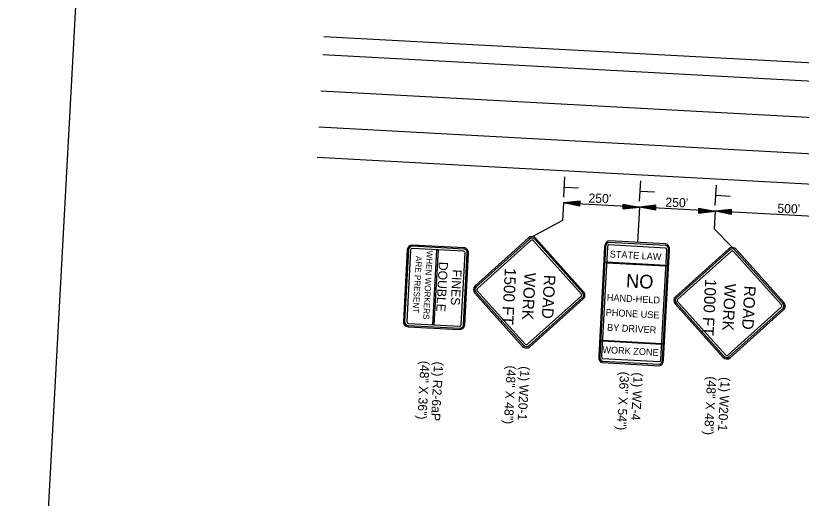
# Model space of a CAD drawing. Extents: x 879461 to 881100, y 1566470 to 1567598.
# Drawn here: x 879461 to 879979, y 1566961 to 1567279 of the extents above; entities that cross this region are included whole.
import ezdxf

# ---------------------------------------------------------------- set-up
doc = ezdxf.new("R2010")
doc.units = 0
for name, color, linetype in [('P_TC_Signs_Permanent', 7, 'Continuous'), ('P_TC_Signs_Temporary', 7, 'Continuous'), ('R_Annotation', 7, 'Continuous'), ('R_Draft', 7, 'Continuous'), ('R_No Plot', 7, 'Continuous')]:
    doc.layers.add(name, color=color, linetype=linetype)

msp = doc.modelspace()

# ---------------------------------------------------------------- linework, layer by layer
at = {"layer": 'P_TC_Signs_Permanent'}
for p, q in [((879889.73, 1567127.9), (879852.27, 1567129.94)), ((879889.79, 1567128.9), (879852.33, 1567130.94)), ((879719.32, 1567125.01), (879716.76, 1567077.83)), ((879720.17, 1567124.96), (879717.6, 1567077.78)), ((879721.57, 1567124.89), (879719, 1567077.71)), ((879756.45, 1567124.12), (879722.75, 1567125.95)), ((879756.53, 1567125.52), (879722.83, 1567127.35)), ((879756.58, 1567126.36), (879722.88, 1567128.19)), ((879849.43, 1567127.07), (879845.51, 1567054.83)), ((879850.1, 1567127.04), (879846.17, 1567054.79)), ((879851.22, 1567126.97), (879847.29, 1567054.73)), ((879889.64, 1567126.23), (879852.18, 1567128.26)), ((879886.53, 1567052.6), (879890.46, 1567124.84)), ((879887.65, 1567052.54), (879891.58, 1567124.78)), ((879888.32, 1567052.5), (879892.25, 1567124.74)), ((879754.95, 1567075.75), (879757.52, 1567122.93)), ((879756.35, 1567075.67), (879758.92, 1567122.85)), ((879757.2, 1567075.63), (879759.76, 1567122.81)), ((879719.94, 1567074.27), (879753.64, 1567072.44)), ((879719.99, 1567075.12), (879753.69, 1567073.28)), ((879720.07, 1567076.52), (879753.77, 1567074.69)), ((879848.02, 1567051.67), (879885.48, 1567049.64)), ((879848.11, 1567053.34), (879885.57, 1567051.31)), ((879847.96, 1567050.67), (879885.42, 1567048.63))]:
    msp.add_line(p, q, dxfattribs=at)
for centre, radius, start, end in [((879722.69, 1567124.82), 3.37, 86.8871, 176.8871), ((879722.69, 1567124.82), 2.53, 86.8871, 176.8871), ((879722.69, 1567124.82), 1.12, 86.8871, 176.8871), ((879756.39, 1567122.99), 1.12, 356.8871, 86.8871), ((879756.39, 1567122.99), 2.53, 356.8871, 86.8871), ((879756.39, 1567122.99), 3.37, 356.8871, 86.8871), ((879720.13, 1567077.64), 3.37, 176.8871, 266.8871), ((879720.13, 1567077.64), 2.53, 176.8871, 266.8871), ((879720.13, 1567077.64), 1.12, 176.8871, 266.8871), ((879753.83, 1567075.81), 3.37, 266.8871, 356.8871), ((879753.83, 1567075.81), 2.53, 266.8871, 356.8871), ((879753.83, 1567075.81), 1.13, 266.8871, 356.8871)]:
    msp.add_arc(centre, radius, start, end, dxfattribs=at)
for centre, major_axis, start_param, end_param in [((879852.11, 1567126.93), (0.22, 4.01), 0, 1.570796), ((879852.11, 1567126.93), (0.16, 3.01), 0, 1.570796), ((879852.11, 1567126.93), (0.07, 1.34), 0, 1.570796), ((879889.57, 1567124.89), (0.07, 1.34), 4.712389, 6.283185), ((879889.57, 1567124.89), (0.16, 3.01), 4.712389, 6.283185), ((879889.57, 1567124.89), (0.22, 4.01), 4.712389, 6.283185), ((879848.18, 1567054.68), (-0.22, -4.01), 4.712389, 6.283185), ((879848.18, 1567054.68), (-0.16, -3.01), 4.712389, 6.283185), ((879848.18, 1567054.68), (-0.07, -1.34), 4.712389, 6.283185), ((879885.64, 1567052.65), (-0.22, -4.01), 0, 1.570796), ((879885.64, 1567052.65), (-0.16, -3.01), 0, 1.570796), ((879885.64, 1567052.65), (-0.07, -1.34), 0, 1.570796)]:
    msp.add_ellipse(centre, major_axis=major_axis, ratio=0.666667, start_param=start_param, end_param=end_param, dxfattribs=at)
at = {"layer": 'P_TC_Signs_Temporary'}
for p, q in [((879764.09, 1567101.3), (879799.27, 1567132.85)), ((879764.72, 1567100.61), (879799.89, 1567132.15)), ((879765.59, 1567099.63), (879800.77, 1567131.18)), ((879802.36, 1567131.09), (879833.9, 1567095.91)), ((879803.33, 1567131.97), (879834.88, 1567096.79)), ((879804.03, 1567132.59), (879835.58, 1567097.42)), ((879896.12, 1567094.12), (879931.3, 1567125.67)), ((879896.75, 1567093.43), (879931.92, 1567124.97)), ((879897.62, 1567092.45), (879932.8, 1567124)), ((879934.39, 1567123.91), (879965.93, 1567088.73)), ((879935.36, 1567124.79), (879966.91, 1567089.61)), ((879936.06, 1567125.41), (879967.61, 1567090.24)), ((879797.05, 1567062.86), (879765.51, 1567098.04)), ((879795.38, 1567061.36), (879763.83, 1567096.54)), ((879796.08, 1567061.99), (879764.53, 1567097.16)), ((879833.82, 1567094.32), (879798.64, 1567062.78)), ((879834.69, 1567093.35), (879799.52, 1567061.8)), ((879835.32, 1567092.65), (879800.14, 1567061.1)), ((879927.41, 1567054.18), (879895.86, 1567089.36)), ((879928.11, 1567054.81), (879896.56, 1567089.98)), ((879929.08, 1567055.68), (879897.54, 1567090.86)), ((879965.85, 1567087.14), (879930.67, 1567055.6)), ((879966.72, 1567086.17), (879931.55, 1567054.62)), ((879967.35, 1567085.47), (879932.17, 1567053.92))]:
    msp.add_line(p, q, dxfattribs=at)
for centre, radius, start, end in [((879801.52, 1567130.34), 3.38, 41.8871, 131.8871), ((879801.52, 1567130.34), 2.44, 41.8871, 131.8871), ((879801.52, 1567130.34), 1.12, 41.8871, 131.8871), ((879933.55, 1567123.16), 3.38, 41.8871, 131.8871), ((879933.55, 1567123.16), 2.44, 41.8871, 131.8871), ((879933.55, 1567123.16), 1.12, 41.8871, 131.8871), ((879766.34, 1567098.79), 3.38, 131.8871, 221.8871), ((879766.34, 1567098.79), 2.44, 131.8871, 221.8871), ((879766.34, 1567098.79), 1.13, 131.8871, 221.8871), ((879833.07, 1567095.16), 1.13, 311.8871, 41.8871), ((879833.07, 1567095.16), 2.44, 311.8871, 41.8871), ((879833.07, 1567095.16), 3.38, 311.8871, 41.8871), ((879898.37, 1567091.61), 3.38, 131.8871, 221.8871), ((879898.37, 1567091.61), 2.44, 131.8871, 221.8871), ((879898.37, 1567091.61), 1.13, 131.8871, 221.8871), ((879965.1, 1567087.98), 1.13, 311.8871, 41.8871), ((879965.1, 1567087.98), 2.44, 311.8871, 41.8871), ((879965.1, 1567087.98), 3.38, 311.8871, 41.8871), ((879797.89, 1567063.62), 2.44, 221.8871, 311.8871), ((879797.89, 1567063.62), 1.12, 221.8871, 311.8871), ((879797.89, 1567063.62), 3.38, 221.8871, 311.8871), ((879929.92, 1567056.43), 3.38, 221.8871, 311.8871), ((879929.92, 1567056.43), 2.44, 221.8871, 311.8871), ((879929.92, 1567056.43), 1.12, 221.8871, 311.8871)]:
    msp.add_arc(centre, radius, start, end, dxfattribs=at)
at = {"layer": 'R_Draft'}
for p, q in [((879664.27, 1567265.81), (880097.64, 1567242.24)), ((879663.62, 1567253.86), (880096.99, 1567230.29)), ((879662.32, 1567229.96), (880095.69, 1567206.39)), ((879661.02, 1567206.05), (880094.39, 1567182.48)), ((879659.94, 1567186.13), (880093.31, 1567162.57)), ((879822.55, 1567159.76), (879823.28, 1567173.21)), ((879872.47, 1567157.05), (879873.2, 1567170.49)), ((879823.1, 1567166.44), (879832.28, 1567165.94)), ((879922.4, 1567154.33), (879923.13, 1567167.78)), ((879873.03, 1567163.73), (879882.21, 1567163.23)), ((879922.96, 1567161.01), (879932.13, 1567160.51)), ((879822.34, 1567155.92), (879821.7, 1567144.29)), ((879833.27, 1567157.13), (879822.34, 1567155.92)), ((879833.15, 1567153.87), (879822.34, 1567155.92)), ((879922.19, 1567150.49), (879822.46, 1567155.88)), ((879833.26, 1567156.86), (879824.15, 1567155.85)), ((879833.16, 1567154.14), (879824.15, 1567155.85)), ((879833.25, 1567156.58), (879826.02, 1567155.78)), ((879833.17, 1567154.42), (879826.02, 1567155.78)), ((879833.24, 1567156.31), (879827.83, 1567155.71)), ((879833.18, 1567154.69), (879827.83, 1567155.71)), ((879833.23, 1567156.03), (879829.68, 1567155.64)), ((879833.19, 1567154.97), (879829.68, 1567155.64)), ((879833.22, 1567155.76), (879831.49, 1567155.57)), ((879833.2, 1567155.24), (879831.49, 1567155.57)), ((879833.15, 1567153.87), (879833.27, 1567157.13)), ((879861.51, 1567155.23), (879861.39, 1567151.97)), ((879861.5, 1567154.96), (879870.51, 1567153.25)), ((879861.51, 1567155.23), (879872.32, 1567153.18)), ((879861.39, 1567151.97), (879872.32, 1567153.18)), ((879861.4, 1567152.24), (879870.51, 1567153.25)), ((879861.41, 1567152.52), (879868.64, 1567153.32)), ((879861.42, 1567152.79), (879866.83, 1567153.39)), ((879861.43, 1567153.07), (879864.98, 1567153.46)), ((879861.44, 1567153.34), (879863.17, 1567153.53)), ((879861.46, 1567153.85), (879863.17, 1567153.53)), ((879861.47, 1567154.13), (879864.98, 1567153.46)), ((879861.48, 1567154.41), (879866.83, 1567153.39)), ((879861.49, 1567154.68), (879868.64, 1567153.32)), ((879872.32, 1567153.18), (879871.06, 1567129.92)), ((879883.26, 1567154.4), (879872.32, 1567153.18)), ((879883.13, 1567151.14), (879872.32, 1567153.18)), ((879883.25, 1567154.12), (879874.14, 1567153.12)), ((879883.14, 1567151.4), (879874.14, 1567153.12)), ((879883.24, 1567153.85), (879876.01, 1567153.04)), ((879883.15, 1567151.69), (879876.01, 1567153.04)), ((879883.23, 1567153.57), (879877.82, 1567152.97)), ((879883.16, 1567151.96), (879877.82, 1567152.97)), ((879883.22, 1567153.3), (879879.66, 1567152.9)), ((879883.17, 1567152.24), (879879.66, 1567152.9)), ((879883.21, 1567153.02), (879881.48, 1567152.83)), ((879883.19, 1567152.51), (879881.48, 1567152.83)), ((879883.13, 1567151.14), (879883.26, 1567154.4)), ((879911.38, 1567152.53), (879911.25, 1567149.27)), ((879911.25, 1567149.27), (879922.19, 1567150.49)), ((879911.26, 1567149.54), (879920.37, 1567150.55)), ((879911.27, 1567149.82), (879918.51, 1567150.63)), ((879911.28, 1567150.09), (879916.69, 1567150.69)), ((879911.29, 1567150.37), (879914.85, 1567150.77)), ((879911.3, 1567150.65), (879913.04, 1567150.83)), ((879911.33, 1567151.16), (879913.04, 1567150.83)), ((879911.34, 1567151.43), (879914.85, 1567150.77)), ((879911.35, 1567151.71), (879916.69, 1567150.69)), ((879911.36, 1567151.98), (879918.51, 1567150.63)), ((879911.37, 1567152.26), (879920.37, 1567150.55)), ((879911.38, 1567152.53), (879922.19, 1567150.49)), ((879922.19, 1567150.49), (879921.56, 1567138.86)), ((879933.13, 1567151.7), (879922.19, 1567150.49)), ((880022.04, 1567145.06), (879922.19, 1567150.49)), ((879933, 1567148.44), (879922.19, 1567150.49)), ((879933.11, 1567151.43), (879924.01, 1567150.42)), ((879933.01, 1567148.71), (879924.01, 1567150.42)), ((879933.1, 1567151.15), (879925.87, 1567150.34)), ((879933.02, 1567148.99), (879925.87, 1567150.34)), ((879933.09, 1567150.88), (879927.69, 1567150.28)), ((879933.03, 1567149.26), (879927.69, 1567150.28)), ((879933.08, 1567150.6), (879929.53, 1567150.2)), ((879933.04, 1567149.54), (879929.53, 1567150.2)), ((879933.07, 1567150.33), (879931.35, 1567150.14)), ((879933.05, 1567149.81), (879931.35, 1567150.14)), ((879933, 1567148.44), (879933.13, 1567151.7)), ((879821.7, 1567144.29), (879801.7, 1567133.71)), ((879921.56, 1567138.86), (879933.73, 1567126.53)), ((879846.82, 1567067.73), (879850.18, 1567129.59)), ((879736.21, 1567075.64), (879738.9, 1567125.07)), ((879739.6, 1567125.03), (879736.92, 1567075.6)), ((879738.9, 1567125.07), (879739.6, 1567125.03)), ((879850.64, 1567116.31), (879850.68, 1567117.02)), ((879889.88, 1567114.18), (879850.64, 1567116.31)), ((879850.68, 1567117.02), (879889.92, 1567114.88)), ((879889.92, 1567114.88), (879889.88, 1567114.18)), ((879736.92, 1567075.6), (879735.51, 1567075.68)), ((879736.92, 1567075.6), (879736.21, 1567075.64)), ((879847.83, 1567064.7), (879847.87, 1567065.4)), ((879887.07, 1567062.57), (879847.83, 1567064.7)), ((879847.87, 1567065.4), (879887.11, 1567063.27)), ((879887.11, 1567063.27), (879887.07, 1567062.57))]:
    msp.add_line(p, q, dxfattribs=at)
at = {"layer": 'R_No Plot'}
msp.add_lwpolyline([(881099.91, 1567310.44), (881054.22, 1566470.26), (879461.22, 1566556.89), (879517.82, 1567597.67), (880700.13, 1567533.37), (880697.45, 1567484.05), (880874.78, 1567474.4), (880873.82, 1567456.58), (880891.99, 1567455.59), (880892.17, 1567458.84), (880969.72, 1567454.62)], dxfattribs=at)

# ---------------------------------------------------------------- texts
at = {"layer": 'P_TC_Signs_Permanent'}
for s, height, rotation, p in [('WHEN WORKERS', 4, 266.8871, (879732.21, 1567124.61)), ('STATE LAW', 4.5, 356.8871, (879852.71, 1567120.04)), ('ARE PRESENT', 4, 266.8871, (879725, 1567121.06)), ('DOUBLE', 6, 266.8871, (879740.21, 1567117.25)), ('FINES', 6, 266.8871, (879749.23, 1567112.19)), ('NO', 9, 356.8871, (879863.34, 1567100.29)), ('HAND-HELD', 4.5, 356.8871, (879850.77, 1567091.47)), ('PHONE USE', 4.5, 356.8871, (879850.05, 1567081.63)), ('BY DRIVER', 4.5, 356.8871, (879850.96, 1567071.71)), ('WORK ZONE', 4.5, 356.8871, (879847.85, 1567057.07))]:
    msp.add_text(s, height=height, rotation=rotation, dxfattribs=at).set_placement(p)
at = {"layer": 'P_TC_Signs_Temporary'}
for s, p in [('1500 FT', (879783.73, 1567113.16)), ('WORK', (879796.61, 1567110.15)), (' ROAD ', (879809.72, 1567111.48)), ('1000 FT', (879915.76, 1567105.98)), ('WORK', (879928.64, 1567102.97)), (' ROAD ', (879941.75, 1567104.3))]:
    msp.add_text(s, height=7.5, rotation=266.8871, dxfattribs=at).set_placement(p)
at = {"layer": 'R_Annotation'}
for s, p in [('(48" X 36")', (879728.1, 1567051.97)), ('(1) R2-6aP', (879737.08, 1567051.48)), ('(48" X 48")', (879785.07, 1567048.87)), ('(1) W20-1', (879794.06, 1567048.38)), ('(36" X 54")', (879859.62, 1567044.81)), ('(1) WZ-4', (879868.61, 1567044.32)), ('(48" X 48")', (879917.1, 1567041.69)), ('(1) W20-1', (879926.09, 1567041.2))]:
    msp.add_text(s, height=6, rotation=266.8871, dxfattribs=at).set_placement(p)
at = {"layer": 'R_Draft'}
for s, p in [("250'", (879838.72, 1567156.23)), ("250'", (879889.42, 1567153.47)), ("500'", (879963.24, 1567149.45))]:
    msp.add_text(s, height=6, rotation=358.1175, dxfattribs=at).set_placement(p)

doc.saveas('drawing.dxf')
